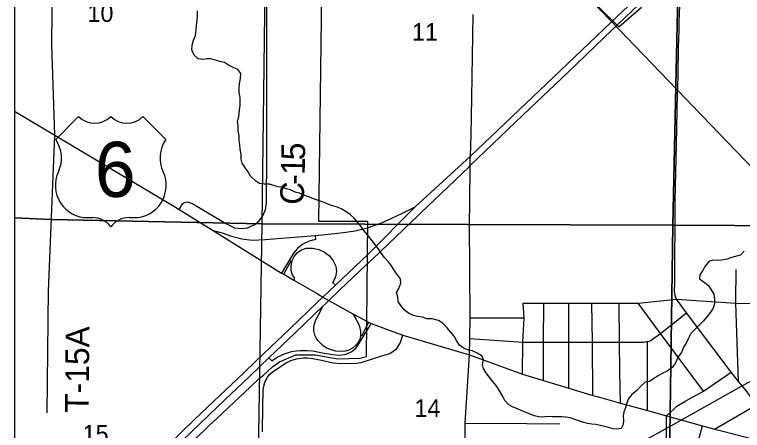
# Model space of a CAD drawing. Extents: x -6.2 to 37.4, y 0.2 to 22.2.
# Drawn here: x 1.681 to 2.552, y 17.135 to 17.632 of the extents above; entities that cross this region are included whole.
import ezdxf

# ---------------------------------------------------------------- set-up
doc = ezdxf.new("R2010")
doc.units = 0
for name, color, linetype in [('GM_X_City_Street', 7, 'Continuous'), ('GM_X_Corporation', 7, 'Continuous'), ('GM_X_County_Road', 7, 'Continuous'), ('GM_X_County_Road_Text', 7, 'Continuous'), ('GM_X_Interchange_Ramps', 7, 'Continuous'), ('GM_X_Minor_River', 7, 'Continuous'), ('GM_X_Rail_Line', 7, 'Continuous'), ('GM_X_Section', 7, 'Continuous'), ('GM_X_Section_Text', 7, 'Continuous'), ('GM_X_State_Route', 7, 'Continuous'), ('GM_X_Township_Road', 7, 'Continuous'), ('GM_X_Township_Road_Text', 7, 'Continuous'), ('GM_X_US_Location', 7, 'Continuous'), ('GM_X_US_Route', 7, 'Continuous'), ('GM_X_US_Shield', 7, 'Continuous'), ('SH_Cut_Line', 7, 'Continuous'), ('SH_Data', 7, 'Continuous')]:
    doc.layers.add(name, color=color, linetype=linetype)

msp = doc.modelspace()

# ---------------------------------------------------------------- linework, layer by layer
at = {"layer": 'GM_X_City_Street'}
for p, q in [((2.22616, 17.26961), (2.29092, 17.26961)), ((2.14573, 17.24924), (2.22529, 17.22542)), ((2.43826, 17.15893), (2.43818, 17.24164)), ((2.51833, 17.13682), (2.56864, 17.16562)), ((2.49427, 17.10375), (2.50408, 17.14076))]:
    msp.add_line(p, q, dxfattribs=at)
for points in [[(2.54711, 17.19378), (2.54398, 17.28716), (2.54402, 17.28985), (2.5446, 17.32759)], [(2.54398, 17.28716), (2.56219, 17.28688), (2.57472, 17.28668), (2.59293, 17.28641), (2.59554, 17.28767), (2.59686, 17.2903), (2.59671, 17.2954), (2.5973, 17.29832), (2.60065, 17.29919), (2.618, 17.29905), (2.66874, 17.3008)], [(2.28965, 17.28745), (2.31414, 17.28742), (2.34432, 17.28738), (2.37184, 17.28735), (2.40448, 17.28731), (2.42707, 17.28729), (2.47322, 17.29198), (2.54398, 17.28716)], [(2.28858, 17.20262), (2.28906, 17.24083), (2.29092, 17.26961), (2.28965, 17.28745)], [(2.31401, 17.19492), (2.31407, 17.24083), (2.31414, 17.28742)], [(2.34413, 17.18581), (2.34423, 17.24083), (2.34432, 17.28738)], [(2.37301, 17.17707), (2.37234, 17.24082), (2.37184, 17.28735)], [(2.40616, 17.16779), (2.40512, 17.20574), (2.40484, 17.24082), (2.40448, 17.28731)], [(2.5055, 17.1822), (2.45399, 17.25121), (2.42707, 17.28729)], [(2.08561, 17.27443), (2.10441, 17.26442), (2.10756, 17.263), (2.14573, 17.24924)], [(2.22573, 17.24489), (2.28906, 17.24083), (2.31407, 17.24083), (2.34423, 17.24083), (2.37234, 17.24082), (2.40484, 17.24082), (2.43337, 17.24081), (2.43679, 17.24133), (2.43818, 17.24164), (2.44156, 17.2424), (2.45399, 17.25121), (2.48521, 17.27558)], [(2.22529, 17.22542), (2.28858, 17.20262), (2.31401, 17.19492), (2.34413, 17.18581), (2.37301, 17.17707), (2.37791, 17.17559), (2.40616, 17.16779), (2.43826, 17.15893), (2.46118, 17.1526), (2.50408, 17.14076), (2.51833, 17.13682), (2.52684, 17.13447), (2.60157, 17.1157)], [(2.46118, 17.1526), (2.4699, 17.1607), (2.47337, 17.16406), (2.4841, 17.17035), (2.5055, 17.1822), (2.53856, 17.20476)], [(2.46551, 16.88713), (2.46439, 16.91117), (2.46167, 16.93318), (2.46166, 16.93869), (2.46162, 16.96661), (2.46162, 16.97042), (2.46157, 17.00466), (2.46146, 17.0457), (2.46137, 17.08188), (2.46132, 17.09991), (2.46118, 17.1526)], [(2.22026, 17.14364), (2.29412, 17.14338), (2.33355, 17.14323)]]:
    msp.add_lwpolyline(points, dxfattribs=at)
at = {"layer": 'GM_X_Corporation'}
for points in [[(1.88863, 17.11704), (1.90859, 17.13599), (1.91376, 17.1409), (1.92293, 17.14959), (1.95082, 17.17554), (1.96248, 17.1865), (1.97414, 17.19747), (1.97861, 17.20122), (1.99009, 17.21152), (1.99793, 17.21704), (2.01738, 17.22553), (2.04045, 17.22538), (2.06791, 17.22058), (2.09407, 17.22167), (2.10196, 17.2235), (2.10345, 17.38507), (2.04508, 17.38501), (2.04865, 17.65851)], [(2.3625, 17.65873), (2.40407, 17.61767), (2.43099, 17.64147)]]:
    msp.add_lwpolyline(points, dxfattribs=at)
at = {"layer": 'GM_X_County_Road'}
msp.add_line((1.98229, 17.41391), (1.9827, 17.45737), dxfattribs=at)
for points in [[(1.9827, 17.45737), (1.98274, 17.46142), (1.983, 17.88391), (1.98635, 18.09451), (1.98794, 18.14401), (1.99016, 18.17491), (2.01317, 18.38522)], [(2.22812, 17.53338), (2.22986, 17.63217), (2.22987, 17.63267)], [(2.22627, 17.45898), (2.22642, 17.46302), (2.22732, 17.4882), (2.22812, 17.53338)], [(2.22529, 17.22542), (2.22573, 17.24489), (2.22616, 17.26961), (2.22551, 17.38314), (2.2258, 17.40689), (2.22618, 17.45179), (2.22624, 17.45798), (2.22627, 17.45898)], [(1.87775, 17.39952), (1.88169, 17.40597), (1.88372, 17.40788), (1.88771, 17.40843), (1.89274, 17.40684), (1.89881, 17.4034), (1.93364, 17.38259), (1.94409, 17.37742), (1.95251, 17.37661), (1.95971, 17.37752), (1.96833, 17.38127), (1.97371, 17.38584), (1.97797, 17.39182), (1.98101, 17.39882), (1.98223, 17.40735), (1.98229, 17.41391)], [(1.9774, 17.13354), (1.97798, 17.16415), (1.97832, 17.18226), (1.97878, 17.1865), (1.9803, 17.19259), (1.98304, 17.19858), (1.98649, 17.20263), (1.99177, 17.20689), (2.00577, 17.21582), (2.01165, 17.21866), (2.01824, 17.22069), (2.02606, 17.2218), (2.03143, 17.22191), (2.03752, 17.2212), (2.04807, 17.21927), (2.06201, 17.21607), (2.07146, 17.21513), (2.09035, 17.21562), (2.0958, 17.21648), (2.12021, 17.22454), (2.1299, 17.22695), (2.13778, 17.23264), (2.14215, 17.23942), (2.14573, 17.24924)], [(2.22312, 16.79629), (2.218, 16.87596), (2.2184, 16.903), (2.21862, 16.93652), (2.22293, 16.97418), (2.22354, 17.00951), (2.22456, 17.04222), (2.21988, 17.08726), (2.22007, 17.11581), (2.22026, 17.14364), (2.22529, 17.22542)]]:
    msp.add_lwpolyline(points, dxfattribs=at)
at = {"layer": 'GM_X_Interchange_Ramps'}
for points in [[(2.04042, 17.36828), (2.04091, 17.36341), (2.03346, 17.36142), (2.02569, 17.35786), (2.01942, 17.35269), (2.01465, 17.34727), (2.0016, 17.3252), (2.00047, 17.32328)], [(2.01494, 17.31489), (2.01622, 17.31708), (2.01358, 17.32101), (2.01186, 17.32637), (2.01174, 17.33174), (2.01313, 17.33848), (2.01556, 17.34313), (2.01901, 17.3476), (2.02354, 17.35065), (2.03004, 17.35292), (2.03749, 17.353), (2.04508, 17.35152), (2.0516, 17.34827), (2.05767, 17.34397), (2.0623, 17.33797), (2.0654, 17.33161), (2.06607, 17.3251), (2.06488, 17.31879), (2.06241, 17.31349), (2.06147, 17.31207), (2.06476, 17.30877)], [(2.00301, 17.32186), (2.00406, 17.3237), (2.01245, 17.33884), (2.01313, 17.33848)], [(2.10246, 17.26021), (2.09621, 17.24803), (2.09487, 17.24853)], [(2.10441, 17.26442), (2.10335, 17.26195), (2.10246, 17.26021)], [(2.10248, 17.2541), (2.10644, 17.26048), (2.10756, 17.263)], [(1.98523, 17.22192), (1.98878, 17.21826), (1.99519, 17.22263), (2.00474, 17.22709), (2.01375, 17.22978), (2.02271, 17.23085), (2.03072, 17.23093), (2.03827, 17.23015), (2.04715, 17.22851), (2.06167, 17.22589), (2.07004, 17.22535), (2.07776, 17.22641), (2.08462, 17.22971), (2.08962, 17.23388), (2.09286, 17.23859), (2.10248, 17.2541)]]:
    msp.add_lwpolyline(points, dxfattribs=at)
at = {"layer": 'GM_X_Minor_River'}
for points in [[(1.89307, 17.59017), (1.89345, 17.59604), (1.89514, 17.60168), (1.89722, 17.60731), (1.89838, 17.61392), (1.89875, 17.61979), (1.89949, 17.62527), (1.89988, 17.63152), (1.89986, 17.63683)], [(2.24491, 17.20427), (2.24203, 17.2091), (2.24105, 17.21406), (2.24197, 17.21916), (2.24041, 17.22395), (2.23521, 17.22733), (2.22905, 17.23037), (2.22395, 17.23128), (2.21889, 17.23315), (2.21332, 17.23711), (2.20989, 17.24253), (2.20683, 17.24775), (2.20244, 17.253), (2.19805, 17.25807), (2.19329, 17.26334), (2.18827, 17.26672), (2.18074, 17.26866), (2.1741, 17.26867), (2.16904, 17.27054), (2.163, 17.27148), (2.15791, 17.27258), (2.15231, 17.27522), (2.14713, 17.27955), (2.1433, 17.28441), (2.13985, 17.28926), (2.13965, 17.29496), (2.13791, 17.29995), (2.14073, 17.30499), (2.1432, 17.31136), (2.1426, 17.31632), (2.13896, 17.32117), (2.13551, 17.32602), (2.13209, 17.33182), (2.12827, 17.33687), (2.1235, 17.34214), (2.11968, 17.34719), (2.11605, 17.35261), (2.11205, 17.35805), (2.1073, 17.3637), (2.10347, 17.36875), (2.0989, 17.3742), (2.09508, 17.37925), (2.09144, 17.3841), (2.08742, 17.38897), (2.08244, 17.39349), (2.07743, 17.39706), (2.0724, 17.39987), (2.06716, 17.40211), (2.06151, 17.40361), (2.05514, 17.40609), (2.05008, 17.40814), (2.04408, 17.41022), (2.0377, 17.41231), (2.03283, 17.41436), (2.02664, 17.41664), (2.02178, 17.41906), (2.01669, 17.41998), (2.01128, 17.42299), (2.00639, 17.42409), (2.00113, 17.42595), (1.99621, 17.42629), (1.99095, 17.42797), (1.98588, 17.42946), (1.97962, 17.42946), (1.97396, 17.43039), (1.96913, 17.43376), (1.96342, 17.43925), (1.96, 17.44486), (1.95637, 17.45009), (1.95329, 17.45493), (1.95212, 17.45971), (1.95191, 17.46503), (1.95078, 17.47152), (1.95039, 17.47703), (1.9496, 17.48199), (1.94977, 17.4873), (1.94845, 17.4936), (1.94844, 17.49929), (1.94785, 17.50481), (1.94935, 17.51008), (1.95018, 17.51841), (1.95073, 17.52389), (1.95088, 17.52863), (1.95084, 17.53338), (1.94968, 17.53872), (1.94967, 17.54423), (1.95003, 17.54972), (1.95137, 17.55613), (1.95155, 17.56182), (1.9481, 17.56667), (1.94268, 17.5693), (1.93708, 17.57213), (1.93205, 17.57494), (1.92659, 17.57624), (1.92133, 17.57792), (1.91588, 17.57961), (1.91113, 17.57937), (1.90599, 17.57877), (1.9007, 17.5795), (1.89572, 17.58402), (1.89307, 17.59017)], [(2.55418, 17.34946), (2.54966, 17.34467), (2.53895, 17.34196), (2.53358, 17.33985), (2.5269, 17.33872), (2.52158, 17.33832), (2.51666, 17.33885), (2.51168, 17.33729), (2.50732, 17.33154), (2.50412, 17.32614), (2.50112, 17.32129), (2.50077, 17.31637), (2.50615, 17.31241), (2.51115, 17.30865), (2.51459, 17.30343), (2.51765, 17.29821), (2.5186, 17.29211), (2.51842, 17.28642), (2.51674, 17.28135), (2.51374, 17.27651), (2.5092, 17.27095), (2.50486, 17.26577), (2.50035, 17.26097), (2.49506, 17.25582), (2.49036, 17.25103), (2.48734, 17.24562), (2.4845, 17.23964), (2.48149, 17.23461), (2.47902, 17.22842), (2.47524, 17.22303), (2.47159, 17.21536), (2.46801, 17.21035), (2.462, 17.20617), (2.4568, 17.20367), (2.451, 17.20024), (2.44578, 17.19718), (2.44093, 17.19372), (2.4354, 17.19294), (2.43032, 17.18816), (2.42502, 17.18263), (2.41975, 17.17805), (2.41522, 17.17268), (2.41374, 17.1678), (2.41204, 17.16216), (2.40999, 17.15729), (2.40908, 17.15238), (2.40967, 17.14724), (2.40913, 17.14213), (2.4067, 17.13727), (2.40193, 17.13647), (2.39683, 17.137), (2.39175, 17.13849), (2.38687, 17.13997), (2.38197, 17.14106), (2.3765, 17.14218), (2.37159, 17.14271), (2.36649, 17.14343), (2.36159, 17.14453), (2.35146, 17.14807), (2.34565, 17.15033), (2.34055, 17.15106), (2.33564, 17.15159), (2.32937, 17.1514), (2.32463, 17.15136), (2.31838, 17.15174), (2.31286, 17.15115), (2.30794, 17.15149), (2.30304, 17.15277), (2.29798, 17.15464), (2.29311, 17.15649), (2.28787, 17.15874), (2.28281, 17.16079), (2.27738, 17.16305), (2.27234, 17.16567), (2.26758, 17.17113), (2.26472, 17.17653), (2.26076, 17.18348), (2.25714, 17.1889), (2.25294, 17.19397), (2.24874, 17.19941), (2.24491, 17.20427)]]:
    msp.add_lwpolyline(points, dxfattribs=at)
at = {"layer": 'GM_X_Rail_Line'}
for points in [[(1.68086, 18.39138), (1.68086, 15.3872)], [(2.74311, 17.29369), (2.70698, 17.31188), (2.68409, 17.32333), (2.66304, 17.33884), (2.6228, 17.38391), (2.57443, 17.43783), (2.3732, 17.64689), (2.28495, 17.73849), (2.26501, 17.76139), (2.24507, 17.78688), (2.23547, 17.80461), (2.23252, 17.82973), (2.23363, 17.86555), (2.23949, 18.135), (2.23635, 18.17521), (2.22852, 18.19924), (2.2186, 18.22431), (2.20659, 18.24729), (2.1878, 18.27967), (2.17736, 18.30787)], [(1.68086, 16.70625), (1.76291, 16.75192), (2.22097, 17.00557), (2.46431, 17.13956), (2.55096, 17.18814), (2.74322, 17.29341), (2.78445, 17.31777), (2.81399, 17.33433), (2.83834, 17.3483), (2.85977, 17.36258), (2.89872, 17.39571), (3.02565, 17.50711), (3.14192, 17.60631), (3.24354, 17.69623), (3.29532, 17.73582), (3.33196, 17.76367), (3.37104, 17.79348), (3.41794, 17.82281), (3.45898, 17.84626), (3.52017, 17.87663)]]:
    msp.add_lwpolyline(points, dxfattribs=at)
at = {"layer": 'GM_X_Section'}
for points in [[(1.98357, 17.88548), (2.4793, 17.87866), (2.46846, 17.38053), (1.97719, 17.38234)], [(2.9229, 17.87578), (2.92261, 17.86953), (2.91294, 17.3873), (2.9126, 17.3784), (2.46846, 17.38053), (2.4793, 17.87866)], [(1.97719, 17.38234), (2.46846, 17.38053), (2.46132, 16.87779), (1.96929, 16.87904)], [(2.46846, 17.38053), (2.9126, 17.3784), (2.90397, 16.89028), (2.90372, 16.88668), (2.64683, 16.88866), (2.46132, 16.87779)]]:
    msp.add_lwpolyline(points, close=True, dxfattribs=at)
at = {"layer": 'GM_X_State_Route'}
for points in [[(2.47636, 17.6237), (2.47686, 17.64366), (2.47682, 17.64711), (2.4772, 17.6725)], [(2.47536, 17.58826), (2.47545, 17.59278), (2.4761, 17.61322), (2.47636, 17.6237)], [(2.47437, 17.53799), (2.47447, 17.54202), (2.47536, 17.58826)], [(2.47089, 17.31164), (2.4716, 17.41008), (2.47295, 17.47766), (2.47437, 17.53799)], [(2.59202, 17.13583), (2.56864, 17.16562), (2.5563, 17.18284), (2.54711, 17.19378), (2.53856, 17.20476), (2.48521, 17.27558), (2.47322, 17.29198), (2.47148, 17.29652), (2.47082, 17.3016), (2.47089, 17.31164)]]:
    msp.add_lwpolyline(points, dxfattribs=at)
at = {"layer": 'GM_X_Township_Road'}
for points in [[(1.72887, 17.48807), (1.7254, 17.59684), (1.72711, 17.75706), (1.72986, 17.88966)], [(1.72118, 17.26851), (1.72161, 17.30146), (1.72887, 17.48807)], [(1.71974, 17.15605), (1.72115, 17.26598), (1.72118, 17.26851)]]:
    msp.add_lwpolyline(points, dxfattribs=at)
at = {"layer": 'GM_X_US_Route'}
for p, q in [((2.0108, 17.3659), (2.01574, 17.3663)), ((2.01574, 17.3663), (2.04042, 17.36828)), ((2.01494, 17.31489), (2.04284, 17.29872)), ((2.04978, 17.28368), (2.05341, 17.28709)), ((2.05715, 17.29043), (2.08561, 17.27443)), ((1.96206, 17.19972), (1.97437, 17.21152))]:
    msp.add_line(p, q, dxfattribs=at)
for points in [[(2.40335, 17.62087), (2.42845, 17.64494), (2.44934, 17.66369), (2.46713, 17.67796)], [(2.1603, 17.40255), (2.22642, 17.46302), (2.30055, 17.53366), (2.35113, 17.58153), (2.40336, 17.63129), (2.4441, 17.66976)], [(2.22473, 17.4504), (2.22618, 17.45179), (2.25301, 17.4774), (2.28961, 17.51236), (2.34299, 17.56327), (2.38625, 17.60447), (2.40335, 17.62087)], [(1.68086, 17.51692), (1.72887, 17.48807), (1.87338, 17.40212)], [(2.10087, 17.33218), (2.10925, 17.3401), (2.16477, 17.39307), (2.16716, 17.39537), (2.19092, 17.41816), (2.22473, 17.4504)], [(1.87338, 17.40212), (1.87775, 17.39952), (1.9184, 17.37429)], [(2.04042, 17.36828), (2.06397, 17.37062), (2.07735, 17.37208), (2.08867, 17.37382), (2.10322, 17.37748), (2.11913, 17.38292), (2.13176, 17.3886), (2.14499, 17.39484), (2.1603, 17.40255)], [(2.06476, 17.30877), (2.1039, 17.34609), (2.1603, 17.40255)], [(1.9184, 17.37429), (2.00047, 17.32328), (2.00301, 17.32186), (2.01494, 17.31489)], [(1.9184, 17.37429), (1.92928, 17.37157), (1.94065, 17.36763), (1.95269, 17.36435), (1.96516, 17.36282), (1.98069, 17.36347), (2.0108, 17.3659)], [(2.05341, 17.28709), (2.05704, 17.2905), (2.0579, 17.29133), (2.05822, 17.29164), (2.05833, 17.29175), (2.05833, 17.29175), (2.07026, 17.30326), (2.10087, 17.33218)], [(2.04338, 17.28847), (2.04993, 17.29462), (2.05064, 17.29529), (2.06476, 17.30877)], [(2.04284, 17.29872), (2.04331, 17.29845), (2.04756, 17.29599)], [(2.04756, 17.29599), (2.04993, 17.29462), (2.05695, 17.29055)], [(1.95708, 17.20587), (1.97883, 17.22671), (2.0104, 17.2568), (2.04338, 17.28847)], [(1.97437, 17.21152), (1.98523, 17.22192), (2.0168, 17.25201), (2.04978, 17.28368)], [(2.08561, 17.27443), (2.08973, 17.26781), (2.09208, 17.26349), (2.09385, 17.25947), (2.09503, 17.25381), (2.09487, 17.24853), (2.09391, 17.24402), (2.09167, 17.24005), (2.08877, 17.23669), (2.08527, 17.23352), (2.08084, 17.23116), (2.07665, 17.22992), (2.07198, 17.22941), (2.06541, 17.22974), (2.05841, 17.23187), (2.05376, 17.23412), (2.04977, 17.23674), (2.04687, 17.23942), (2.04392, 17.24281), (2.04175, 17.24591), (2.04036, 17.24894), (2.03954, 17.25206), (2.039, 17.25459), (2.039, 17.25862), (2.03971, 17.26278), (2.0414, 17.26721), (2.04575, 17.27554), (2.04978, 17.28368)], [(1.68086, 16.95097), (1.70752, 16.97299), (1.73331, 16.99459), (1.75926, 17.01813), (1.78644, 17.04312), (1.81917, 17.07454), (1.8654, 17.11846), (1.8964, 17.14807), (1.92667, 17.1771), (1.95529, 17.20416), (1.95708, 17.20587)], [(1.80831, 17.05318), (1.82558, 17.06975), (1.8718, 17.11367), (1.90281, 17.14328), (1.93307, 17.17232), (1.9617, 17.19938), (1.96206, 17.19972)]]:
    msp.add_lwpolyline(points, dxfattribs=at)
at = {"layer": 'GM_X_US_Shield'}
for p, q in [((1.75757, 17.51048), (1.73011, 17.48302)), ((1.86194, 17.48302), (1.83448, 17.51048)), ((1.76856, 17.38963), (1.77405, 17.38963)), ((1.818, 17.38963), (1.82349, 17.38963))]:
    msp.add_line(p, q, dxfattribs=at)
for points in [[(1.68086, 17.89319), (1.68086, 17.38941), (1.72471, 17.38725), (1.97719, 17.38234), (1.98357, 17.88548)], [(1.68086, 17.38941), (1.68086, 16.89117), (1.96929, 16.87904), (1.97719, 17.38234), (1.72471, 17.38725)]]:
    msp.add_lwpolyline(points, close=True, dxfattribs=at)
for centre, radius, start, end in [((1.7768, 17.5301), 0.02747, 225.573, 314.427), ((1.81525, 17.5301), 0.02747, 225.573, 314.427), ((1.69861, 17.46096), 0.03845, 334.54712, 35.00093), ((1.89344, 17.46096), 0.03845, 144.99907, 205.45288), ((1.76813, 17.42808), 0.03845, 154.83192, 270.63826), ((1.82392, 17.42808), 0.03845, 269.36174, 25.16808), ((1.77405, 17.36217), 0.02747, 36.8699, 90), ((1.818, 17.36217), 0.02747, 90, 143.1301)]:
    msp.add_arc(centre, radius, start, end, dxfattribs=at)
at = {"layer": 'SH_Cut_Line'}
msp.add_lwpolyline([(1.68086, 20.39726), (1.68086, 14.30742)], dxfattribs=at)
at = {"layer": 'SH_Data'}
msp.add_line((1.68086, 21.10742), (1.68086, 14.30742), dxfattribs=at)

# ---------------------------------------------------------------- texts
at = {"layer": 'GM_X_County_Road_Text'}
for s, rotation, p in [('5', 89.08066, (2.02841, 17.45803)), ('1', 88.95389, (2.02809, 17.44046)), ('-', 88.47236, (2.02778, 17.42854)), ('C', 86.97777, (2.02651, 17.40443))]:
    msp.add_text(s, height=0.02841, rotation=rotation, dxfattribs=at).set_placement(p)
at = {"layer": 'GM_X_Section_Text'}
for s, p in [('10', (1.76811, 17.62374)), ('11', (2.15644, 17.60124)), ('14', (2.15936, 17.1514)), ('15', (1.76228, 17.12067))]:
    msp.add_text(s, height=0.020928, rotation=0.00001, dxfattribs=at).set_placement(p)
at = {"layer": 'GM_X_Township_Road_Text'}
msp.add_text('T-15A', height=0.028409, rotation=89.48312, dxfattribs=at).set_placement((1.76955, 17.15619))
at = {"layer": 'GM_X_US_Location'}
for s, p in [('0', (1.79599, 17.44679)), ('/', (1.796, 17.44679))]:
    msp.add_text(s, height=0.0000947, dxfattribs=at).set_placement(p)
msp.add_text('6', height=0.0000947, rotation=0.00001, dxfattribs=at).set_placement((1.78644, 17.42719))
at = {"layer": 'GM_X_US_Shield'}
msp.add_text('6', height=0.06592, dxfattribs=at).set_placement((1.77687, 17.41435))

doc.saveas('drawing.dxf')
